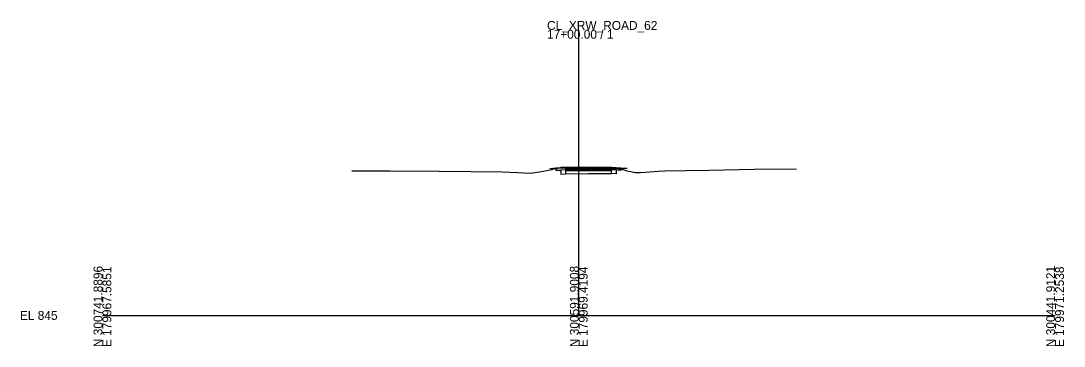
# Model space of a CAD drawing. Extents: x -26 to 303, y 490 to 4093.
# Drawn here: x -25.7 to 302.8, y 1990.3 to 2092.8 of the extents above; entities that cross this region are included whole.
import ezdxf

# ---------------------------------------------------------------- set-up
doc = ezdxf.new("R2010")
doc.units = 0
for name, color, linetype in [('CL_P_Construction', 7, 'Continuous'), ('CM_Corridor_Bottom_Mesh', 7, 'Continuous'), ('CM_Corridor_Top_Mesh', 7, 'Continuous'), ('Default', 7, 'Continuous'), ('DT_P_TIN_Hull', 7, 'Continuous'), ('GK_Cells', 7, 'Continuous'), ('MD_P_Subgrade', 7, 'Continuous'), ('MD_P_Surface_Aggregate_Base', 7, 'Continuous'), ('MD_P_Surface_Asphalt_Concrete_Base', 7, 'Continuous'), ('MD_P_Surface_Asphalt_Concrete_Surface_Course', 7, 'Continuous'), ('MD_P_Surface_Chemically_Stabalized_Subgrade', 7, 'Continuous'), ('MD_P_Surface_Finished_Grade', 7, 'Continuous'), ('XS_X_Ground_Line', 7, 'Continuous')]:
    doc.layers.add(name, color=color, linetype=linetype)

msp = doc.modelspace()

# ---------------------------------------------------------------- linework, layer by layer
at = {"layer": 'CM_Corridor_Bottom_Mesh'}
for points in [[(145.85, 2046.56), (145.85, 2045.89), (144.35, 2045.8), (142.84, 2045.71), (142.84, 2046.38), (140.84, 2046.21)], [(165.25, 2046.27), (163.25, 2046.43), (163.25, 2045.77), (161.75, 2045.86), (160.25, 2045.95), (160.25, 2046.61)]]:
    msp.add_lwpolyline(points, dxfattribs=at)
at = {"layer": 'CM_Corridor_Top_Mesh'}
for points in [[(145.85, 2046.56), (142.84, 2046.38), (140.84, 2046.21)], [(165.25, 2046.27), (163.25, 2046.43), (160.25, 2046.61)]]:
    msp.add_lwpolyline(points, dxfattribs=at)
at = {"layer": 'DT_P_TIN_Hull'}
msp.add_lwpolyline([(145.85, 2046.56), (153.06, 2046.62), (153.19, 2046.62), (153.87, 2046.62), (160.25, 2046.61)], dxfattribs=at)
at = {"layer": 'GK_Cells'}
for p, q in [((150, 2000), (150, 2090)), ((0, 2000), (150, 2000)), ((150, 2000), (300, 2000))]:
    msp.add_line(p, q, dxfattribs=at)
at = {"layer": 'MD_P_Subgrade'}
for points in [[(142.84, 2045.71), (142.84, 2046.38)], [(142.84, 2045.71), (144.35, 2045.8), (144.35, 2044.56), (145.85, 2044.62)], [(163.25, 2045.77), (161.75, 2045.86), (161.75, 2044.62), (160.25, 2044.68)], [(163.25, 2045.77), (163.25, 2046.43)]]:
    msp.add_lwpolyline(points, dxfattribs=at)
at = {"layer": 'MD_P_Surface_Aggregate_Base'}
for points in [[(145.85, 2046.56), (145.85, 2045.89), (142.84, 2045.71), (142.84, 2046.38), (145.85, 2046.56)], [(145.85, 2046.12), (145.85, 2045.62), (153.06, 2045.68), (153.19, 2045.68), (153.87, 2045.68), (160.25, 2045.68), (160.25, 2046.18), (153.87, 2046.18), (153.19, 2046.18), (153.06, 2046.18), (145.85, 2046.12)], [(160.25, 2046.61), (160.25, 2045.95), (163.25, 2045.77), (163.25, 2046.43), (160.25, 2046.61)]]:
    msp.add_lwpolyline(points, dxfattribs=at)
at = {"layer": 'MD_P_Surface_Asphalt_Concrete_Base'}
msp.add_lwpolyline([(145.85, 2046.45), (145.85, 2046.12), (153.06, 2046.18), (153.19, 2046.18), (153.87, 2046.18), (160.25, 2046.18), (160.25, 2046.51), (153.87, 2046.51), (153.19, 2046.51), (153.06, 2046.51), (145.85, 2046.45)], dxfattribs=at)
at = {"layer": 'MD_P_Surface_Asphalt_Concrete_Surface_Course'}
msp.add_lwpolyline([(145.85, 2046.56), (145.85, 2046.45), (153.06, 2046.51), (153.19, 2046.51), (153.87, 2046.51), (160.25, 2046.51), (160.25, 2046.61), (153.87, 2046.62), (153.19, 2046.62), (153.06, 2046.62), (145.85, 2046.56)], dxfattribs=at)
at = {"layer": 'MD_P_Surface_Chemically_Stabalized_Subgrade'}
msp.add_lwpolyline([(145.85, 2045.62), (145.85, 2044.62), (153.06, 2044.68), (153.19, 2044.68), (153.87, 2044.68), (160.25, 2044.68), (160.25, 2045.68), (153.87, 2045.68), (153.19, 2045.68), (153.06, 2045.68), (145.85, 2045.62)], dxfattribs=at)
at = {"layer": 'MD_P_Surface_Finished_Grade'}
for points in [[(142.84, 2046.38), (140.84, 2046.21)], [(163.25, 2046.43), (165.25, 2046.27)]]:
    msp.add_lwpolyline(points, dxfattribs=at)
at = {"layer": 'XS_X_Ground_Line'}
msp.add_lwpolyline([(78.53, 2045.54), (79.22, 2045.54), (90.56, 2045.6), (105.89, 2045.44), (105.9, 2045.43), (105.94, 2045.43), (106.02, 2045.43), (125.95, 2045.22), (130.73, 2045.01), (134.7, 2044.82), (137.6, 2045.28), (139.97, 2045.7), (141.47, 2046.01), (142.24, 2046.17), (142.96, 2046.32), (143.4, 2046.41), (143.83, 2046.5), (144.58, 2046.68), (145.57, 2046.71), (146.48, 2046.74), (149.74, 2046.75), (153.67, 2046.75), (157.1, 2046.61), (160.32, 2046.45), (161.37, 2046.43), (162.23, 2046.41), (163.53, 2046.05), (165.13, 2045.61), (166.33, 2045.35), (167.73, 2045.01), (169.39, 2045.05), (171.01, 2045.1), (174.96, 2045.42), (177.11, 2045.57), (183.96, 2045.69), (191.08, 2045.81), (205.24, 2046.13), (218.51, 2046.24)], dxfattribs=at)

# ---------------------------------------------------------------- texts
at = {"layer": 'CL_P_Construction'}
msp.add_text('X', height=0.1, dxfattribs=at).set_placement((153.16, 2046.57))
at = {"layer": 'Default'}
msp.add_text('-', height=0.0001, dxfattribs=at).set_placement((0, 2000))
at = {"layer": 'GK_Cells'}
for s, p in [('CL_XRW_ROAD_62', (140, 2090)), ('17+00.00 / 1', (140, 2087.2)), ('EL 845', (-26, 1998.6))]:
    msp.add_text(s, height=2.8, dxfattribs=at).set_placement(p)
for s, p in [('N 300741.8896', (0, 1990)), ('E 179967.5851', (2.8, 1990)), ('N 300591.9008', (150, 1990)), ('E 179969.4194', (152.8, 1990)), ('N 300441.9121', (300, 1990)), ('E 179971.2538', (302.8, 1990))]:
    msp.add_text(s, height=2.8, rotation=90, dxfattribs=at).set_placement(p)

doc.saveas('drawing.dxf')
